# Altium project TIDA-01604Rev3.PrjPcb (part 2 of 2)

## Sheet PowerBoard.SchDoc
size 431 x 279 mm; Date: Not shown in title block; ApprovedBy: Not shown in title block; CheckedBy: Not shown in title block; Author: Not shown in title block; CompanyName: Not shown in title block; DrawnBy: G Wang; Engineer: Not shown in title block; Organization: Not shown in title block; Address1: Not shown in title block; Address2: Not shown in title block; Address3: Not shown in title block; Address4: Not shown in title block; DocumentNumber: 1; Revision: Use project parameter SCH_Rev; SheetNumber: 1; SheetTotal: 2; PageSetup: Record=PageOptions¦CenterHorizontal=True¦CenterVertical=True¦PrintScale=1.00¦XCorrection=1.00¦YCorrection=1.00¦PrintKind=0¦BorderSize=5000000¦LeftOffset=0¦BottomOffset=0¦Orientation=2¦PaperLength=1000¦PaperWidth=1000¦Scale=100¦PaperSource=15¦PrintQuality=600¦MediaType=1¦DitherType=10¦PaperKind=Letter¦PrintScaleMode=1
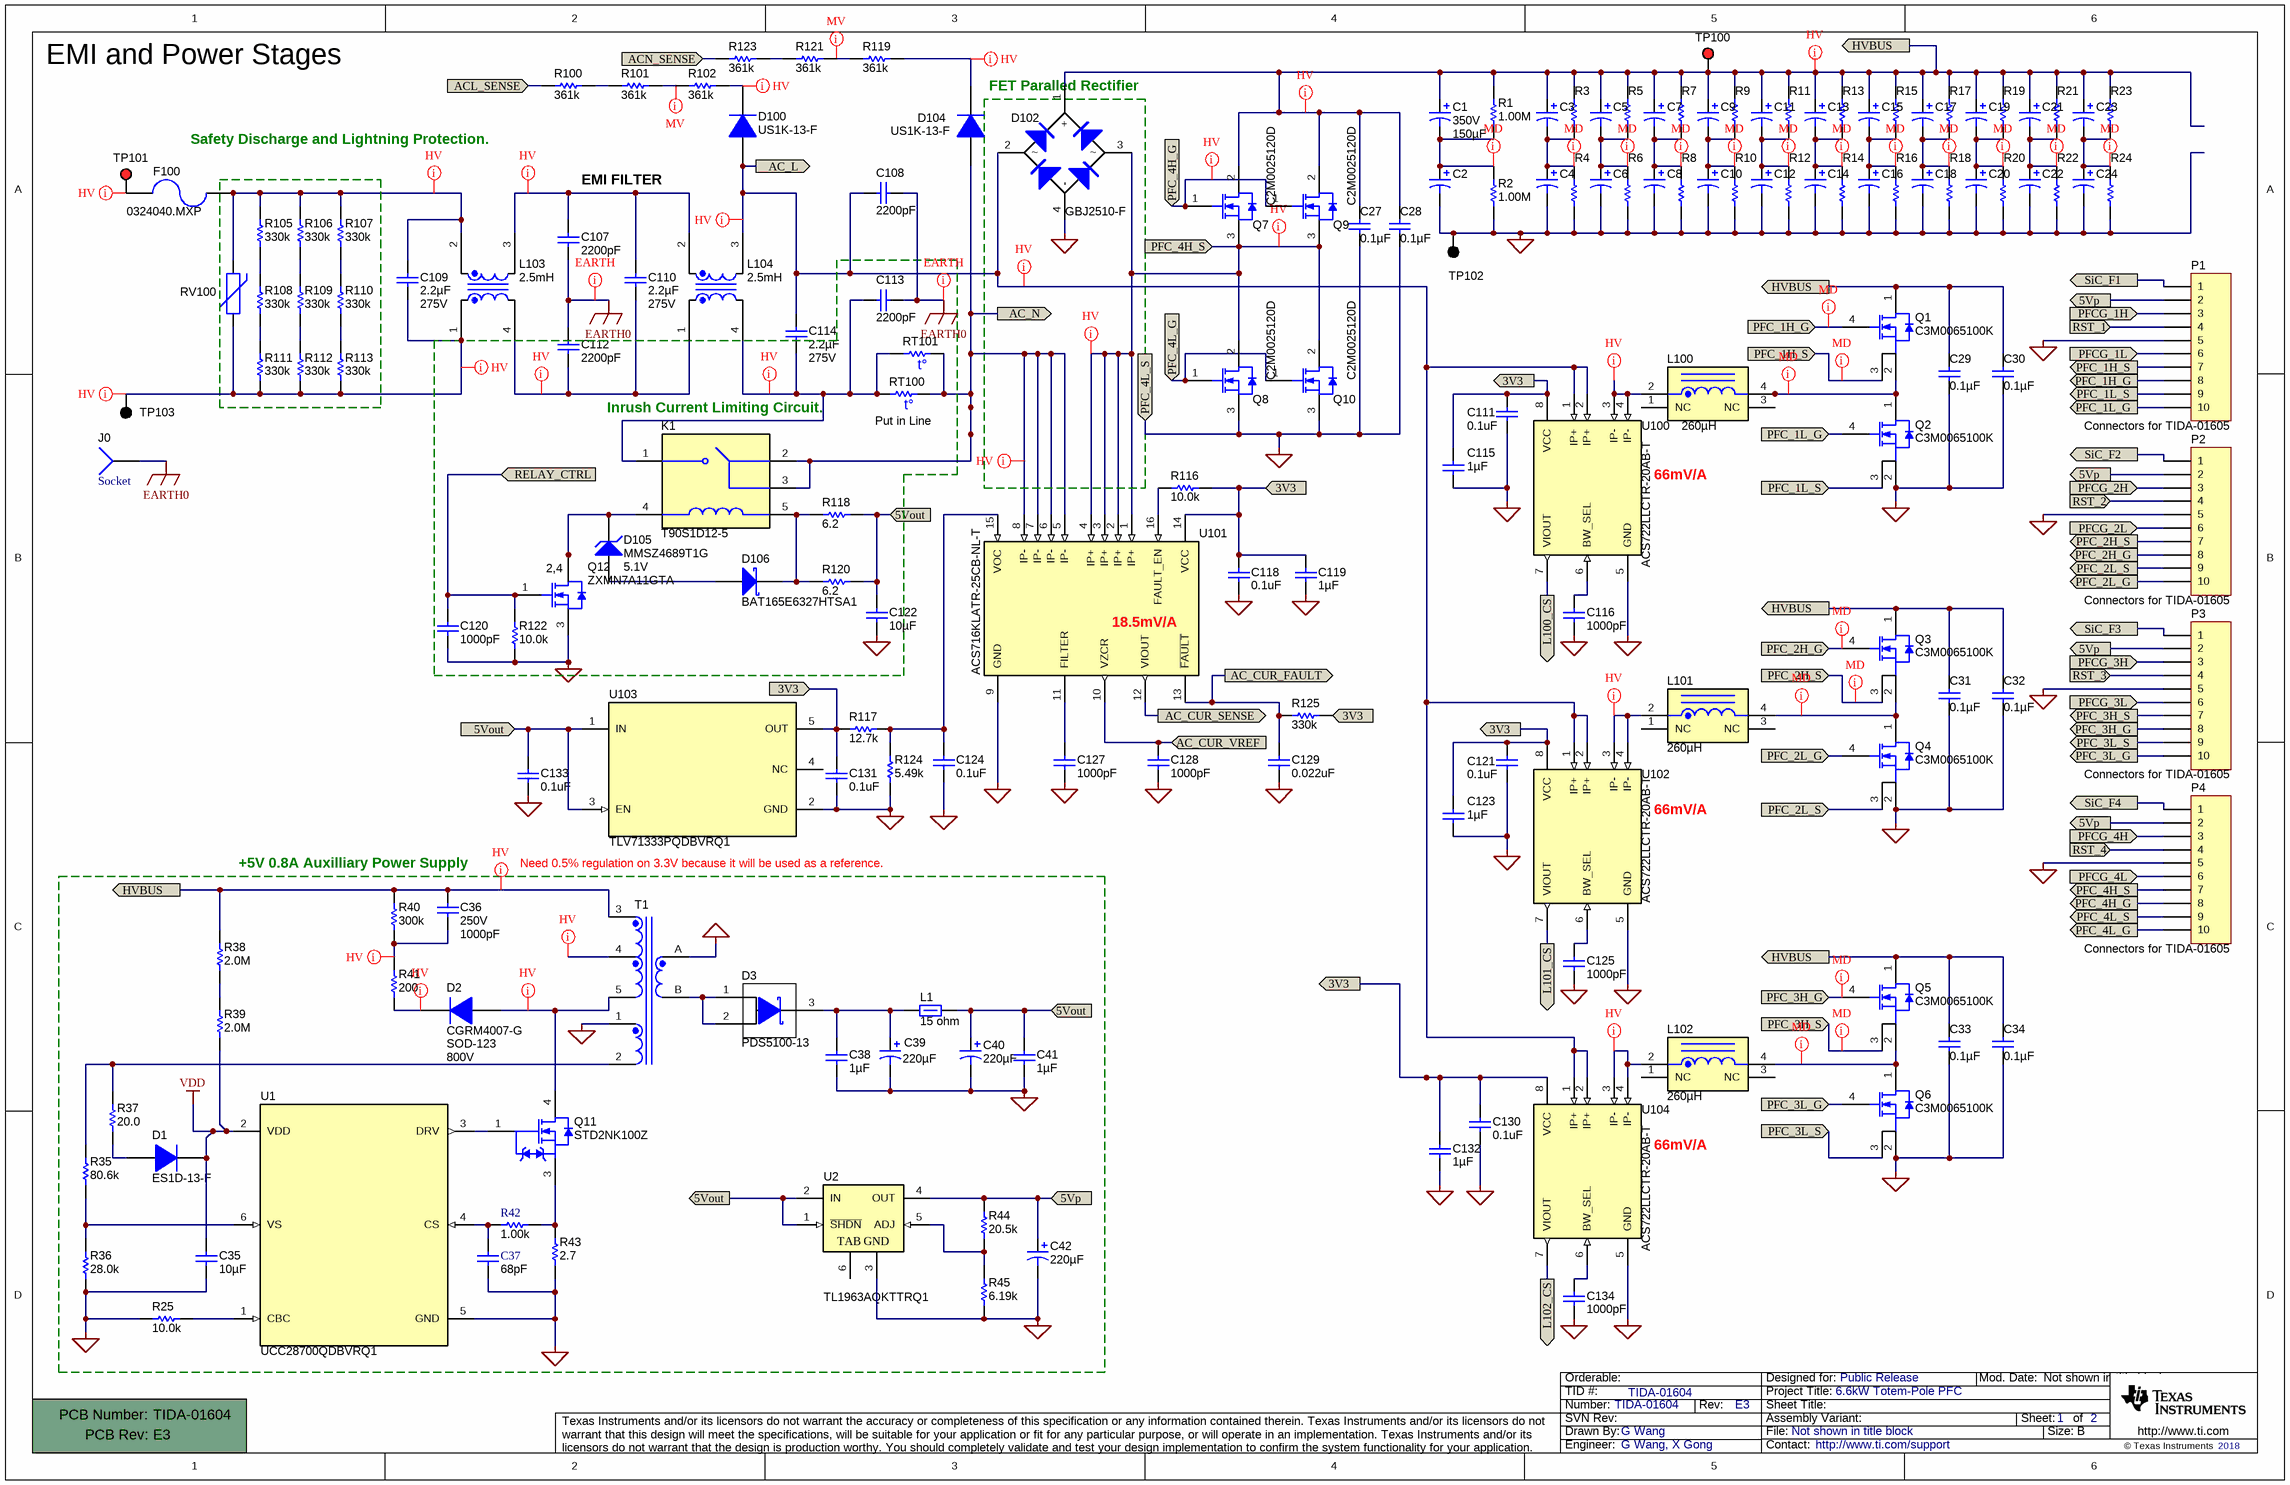
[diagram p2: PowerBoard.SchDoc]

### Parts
!PCB100  Printed Circuit Board  (value not drawn)  (mechanical)
C1  VDC_V: 350V  ValueDisplayed: 150µF  [BXW_1450x4500]  (hidden comment: 350BXW150MEFR14.5X45)
C2  350BXW150MEFR14.5X45  [BXW_1450x4500]  (value not drawn)
C3  350BXW150MEFR14.5X45  [BXW_1450x4500]  (value not drawn)
C4  350BXW150MEFR14.5X45  [BXW_1450x4500]  (value not drawn)
C5  350BXW150MEFR14.5X45  [BXW_1450x4500]  (value not drawn)
C6  350BXW150MEFR14.5X45  [BXW_1450x4500]  (value not drawn)
C7  350BXW150MEFR14.5X45  [BXW_1450x4500]  (value not drawn)
C8  350BXW150MEFR14.5X45  [BXW_1450x4500]  (value not drawn)
C9  350BXW150MEFR14.5X45  [BXW_1450x4500]  (value not drawn)
C10  350BXW150MEFR14.5X45  [BXW_1450x4500]  (value not drawn)
C11  350BXW150MEFR14.5X45  [BXW_1450x4500]  (value not drawn)
C12  350BXW150MEFR14.5X45  [BXW_1450x4500]  (value not drawn)
C13  350BXW150MEFR14.5X45  [BXW_1450x4500]  (value not drawn)
C14  350BXW150MEFR14.5X45  [BXW_1450x4500]  (value not drawn)
C15  350BXW150MEFR14.5X45  [BXW_1450x4500]  (value not drawn)
C16  350BXW150MEFR14.5X45  [BXW_1450x4500]  (value not drawn)
C17  350BXW150MEFR14.5X45  [BXW_1450x4500]  (value not drawn)
C18  350BXW150MEFR14.5X45  [BXW_1450x4500]  (value not drawn)
C19  350BXW150MEFR14.5X45  [BXW_1450x4500]  (value not drawn)
C20  350BXW150MEFR14.5X45  [BXW_1450x4500]  (value not drawn)
C21  350BXW150MEFR14.5X45  [BXW_1450x4500]  (value not drawn)
C22  350BXW150MEFR14.5X45  [BXW_1450x4500]  (value not drawn)
C23  350BXW150MEFR14.5X45  [BXW_1450x4500]  (value not drawn)
C24  350BXW150MEFR14.5X45  [BXW_1450x4500]  (value not drawn)
C27  ValueDisplayed: 0.1µF  [1812]  (hidden comment: VJ1812Y473KXEAT5Z)
C28  ValueDisplayed: 0.1µF  [1812]  (hidden comment: VJ1812Y473KXEAT5Z)
C29  ValueDisplayed: 0.1µF  [1812]  (hidden comment: VJ1812Y473KXEAT5Z)
C30  ValueDisplayed: 0.1µF  [1812]  (hidden comment: VJ1812Y473KXEAT5Z)
C31  ValueDisplayed: 0.1µF  [1812]  (hidden comment: VJ1812Y473KXEAT5Z)
C32  ValueDisplayed: 0.1µF  [1812]  (hidden comment: VJ1812Y473KXEAT5Z)
C33  ValueDisplayed: 0.1µF  [1812]  (hidden comment: VJ1812Y473KXEAT5Z)
C34  ValueDisplayed: 0.1µF  [1812]  (hidden comment: VJ1812Y473KXEAT5Z)
C35  ValueDisplayed: 10µF  [1206_180]  (hidden comment: GRM31CR71E106KA12L)
C36  VDC_V: 250V  ValueDisplayed: 1000pF  [0805_HV]  (hidden comment: C2012X7R2E102K085AA)
C37  ValueDisplayed: 68pF  [0603]  (hidden comment: 06035A680JAT2A)
C38  ValueDisplayed: 1µF  [0603]  (hidden comment: GRM185R60J105KE26D)
C39  ValueDisplayed: 220µF  [7343-30]  (hidden comment: 10TPE220ML)
C40  ValueDisplayed: 220µF  [7343-30]  (hidden comment: 10TPE220ML)
C41  ValueDisplayed: 1µF  [0603]  (hidden comment: GRM185R60J105KE26D)
C42  ValueDisplayed: 220µF  [7343-30]  (hidden comment: 10TPE220ML)
C107  ValueDisplayed: 2200pF  [E_900x700x900]  (hidden comment: DE6E3KJ222MN3A)
C108  ValueDisplayed: 2200pF  [E_900x700x900]  (hidden comment: DE6E3KJ222MN3A)
C109  ValueDisplayed: 2.2µF  Value2: 275V  [WCAP-FTX2_2600x1500x2500]  (hidden comment: 890324026034)
C110  ValueDisplayed: 2.2µF  Value2: 275V  [WCAP-FTX2_2600x1500x2500]  (hidden comment: 890324026034)
C111  ValueDisplayed: 0.1uF  [0402]  (hidden comment: GRM155R70J104KA01D)
C112  ValueDisplayed: 2200pF  [E_900x700x900]  (hidden comment: DE6E3KJ222MN3A)
C113  ValueDisplayed: 2200pF  [E_900x700x900]  (hidden comment: DE6E3KJ222MN3A)
C114  ValueDisplayed: 2.2µF  Value2: 275V  [WCAP-FTX2_2600x1500x2500]  (hidden comment: 890324026034)
C115  ValueDisplayed: 1µF  [0603]  (hidden comment: GRM185R60J105KE26D)
C116  ValueDisplayed: 1000pF  [0603]  (hidden comment: 06035A102KAT2A)
C118  ValueDisplayed: 0.1uF  [0402]  (hidden comment: GRM155R70J104KA01D)
C119  ValueDisplayed: 1µF  [0603]  (hidden comment: GRM185R60J105KE26D)
C120  ValueDisplayed: 1000pF  [0603]  (hidden comment: GRM188R71C102KA01D)
C121  ValueDisplayed: 0.1uF  [0402]  (hidden comment: GRM155R70J104KA01D)
C122  ValueDisplayed: 10µF  [0805_HV]  (hidden comment: 0805YD106KAT2A)
C123  ValueDisplayed: 1µF  [0603]  (hidden comment: GRM185R60J105KE26D)
C124  ValueDisplayed: 0.1uF  [0402]  (hidden comment: GRM155R70J104KA01D)
C125  ValueDisplayed: 1000pF  [0603]  (hidden comment: 06035A102KAT2A)
C127  ValueDisplayed: 1000pF  [0402]  (hidden comment: GRM155R60J102KA01D)
C128  ValueDisplayed: 1000pF  [0402]  (hidden comment: GRM155R60J102KA01D)
C129  ValueDisplayed: 0.022uF  [0402]  (hidden comment: GRM155R70J223KA01D)
C130  ValueDisplayed: 0.1uF  [0402]  (hidden comment: GRM155R70J104KA01D)
C131  ValueDisplayed: 0.1uF  [0402]  (hidden comment: GRM155R70J104KA01D)
C132  ValueDisplayed: 1µF  [0603]  (hidden comment: GRM185R60J105KE26D)
C133  ValueDisplayed: 0.1uF  [0402]  (hidden comment: GRM155R70J104KA01D)
C134  ValueDisplayed: 1000pF  [0603]  (hidden comment: 06035A102KAT2A)
D1  ES1D-13-F  [SMA]
D2  CGRM4007-G  Value2: 800V  [SOD-123]
D3  PDS5100-13  [POWERDI5]
D100  US1K-13-F  [SMA]
D102  GBJ2510-F  [GBJ]
D104  US1K-13-F  [SMA]
D105  MMSZ4689T1G  value 5.1V  [SOD-123]
D106  BAT165E6327HTSA1  [SOD-323]
F100  0324040.MXP  [FUSE_0325_Vertical]
J0  Socket  [PIN1]
K1  T90S1D12-5  [Relay_T90S1]
L1  ValueDisplayed: 15 ohm  [0603]  (hidden comment: MMZ1608R150ATA00)
L100  ValueDisplayed: 260µH  [G184014LF]  (hidden comment: G184014LF)
L101  ValueDisplayed: 260µH  [G184014LF]  (hidden comment: G184014LF)
L102  ValueDisplayed: 260µH  [G184014LF]  (hidden comment: G184014LF)
L103  ValueDisplayed: 2.5mH  [WE-CMBNC_XL]  (hidden comment: 7448052303)
L104  ValueDisplayed: 2.5mH  [WE-CMBNC_XL]  (hidden comment: 7448052303)
P1  PartNumber: Connectors for TIDA-01605  [Driver]  (hidden comment: driver)
P2  PartNumber: Connectors for TIDA-01605  [Driver]  (hidden comment: driver)
P3  PartNumber: Connectors for TIDA-01605  [Driver]  (hidden comment: driver)
P4  PartNumber: Connectors for TIDA-01605  [Driver]  (hidden comment: driver)
Q1  C3M0065100K  [TO-247-4]
Q2  C3M0065100K  [TO-247-4]
Q3  C3M0065100K  [TO-247-4]
Q4  C3M0065100K  [TO-247-4]
Q5  C3M0065100K  [TO-247-4]
Q6  C3M0065100K  [TO-247-4]
Q7  C2M0025120D  [TO-247]
Q8  C2M0025120D  [TO-247]
Q9  C2M0025120D  [TO-247]
Q10  C2M0025120D  [TO-247]
Q11  STD2NK100Z  [DPAK]
Q12  ZXMN7A11GTA  [SOT-223]
R1  ValueDisplayed: 1.00M  [1206]  (hidden comment: CRCW12061M00FKEA)
R2  ValueDisplayed: 1.00M  [1206]  (hidden comment: CRCW12061M00FKEA)
R3  CRCW12061M00FKEA  [1206]  (value not drawn)
R4  CRCW12061M00FKEA  [1206]  (value not drawn)
R5  CRCW12061M00FKEA  [1206]  (value not drawn)
R6  CRCW12061M00FKEA  [1206]  (value not drawn)
R7  CRCW12061M00FKEA  [1206]  (value not drawn)
R8  CRCW12061M00FKEA  [1206]  (value not drawn)
R9  CRCW12061M00FKEA  [1206]  (value not drawn)
R10  CRCW12061M00FKEA  [1206]  (value not drawn)
R11  CRCW12061M00FKEA  [1206]  (value not drawn)
R12  CRCW12061M00FKEA  [1206]  (value not drawn)
R13  CRCW12061M00FKEA  [1206]  (value not drawn)
R14  CRCW12061M00FKEA  [1206]  (value not drawn)
R15  CRCW12061M00FKEA  [1206]  (value not drawn)
R16  CRCW12061M00FKEA  [1206]  (value not drawn)
R17  CRCW12061M00FKEA  [1206]  (value not drawn)
R18  CRCW12061M00FKEA  [1206]  (value not drawn)
R19  CRCW12061M00FKEA  [1206]  (value not drawn)
R20  CRCW12061M00FKEA  [1206]  (value not drawn)
R21  CRCW12061M00FKEA  [1206]  (value not drawn)
R22  CRCW12061M00FKEA  [1206]  (value not drawn)
R23  CRCW12061M00FKEA  [1206]  (value not drawn)
R24  CRCW12061M00FKEA  [1206]  (value not drawn)
R25  ValueDisplayed: 10.0k  [0603]  (hidden comment: CRCW060310K0FKEA)
R35  ValueDisplayed: 80.6k  [0603]  (hidden comment: CRCW060380K6FKEA)
R36  ValueDisplayed: 28.0k  [0603]  (hidden comment: CRCW060328K0FKEA)
R37  ValueDisplayed: 20.0  [0603]  (hidden comment: RC0603FR-0720RL)
R38  ValueDisplayed: 2.0M  [1206]  (hidden comment: CRCW12062M00JNEA)
R39  ValueDisplayed: 2.0M  [1206]  (hidden comment: CRCW12062M00JNEA)
R40  ValueDisplayed: 300k  [1206]  (hidden comment: RC1206FR-07300KL)
R41  ValueDisplayed: 200  [0805_HV]  (hidden comment: ERJ-6GEYJ201V)
R42  value 1.00k  [0603]  (hidden comment: CRCW06031K00FKEA)
R43  ValueDisplayed: 2.7  [0805_HV]  (hidden comment: CRCW08052R70JNEA)
R44  ValueDisplayed: 20.5k  [0603]  (hidden comment: RC0603FR-0720K5L)
R45  ValueDisplayed: 6.19k  [0603]  (hidden comment: RC0603FR-076K19L)
R100  ValueDisplayed: 361k  [0805_HV]  (hidden comment: RT0805BRD07361KL)
R101  ValueDisplayed: 361k  [0805_HV]  (hidden comment: RT0805BRD07361KL)
R102  ValueDisplayed: 361k  [0805_HV]  (hidden comment: RT0805BRD07361KL)
R105  ValueDisplayed: 330k  [1206]  (hidden comment: CRCW1206330KJNEA)
R106  ValueDisplayed: 330k  [1206]  (hidden comment: CRCW1206330KJNEA)
R107  ValueDisplayed: 330k  [1206]  (hidden comment: CRCW1206330KJNEA)
R108  ValueDisplayed: 330k  [1206]  (hidden comment: CRCW1206330KJNEA)
R109  ValueDisplayed: 330k  [1206]  (hidden comment: CRCW1206330KJNEA)
R110  ValueDisplayed: 330k  [1206]  (hidden comment: CRCW1206330KJNEA)
R111  ValueDisplayed: 330k  [1206]  (hidden comment: CRCW1206330KJNEA)
R112  ValueDisplayed: 330k  [1206]  (hidden comment: CRCW1206330KJNEA)
R113  ValueDisplayed: 330k  [1206]  (hidden comment: CRCW1206330KJNEA)
R116  value 10.0k  [0402]  (hidden comment: CRCW040210K0FKED)
R117  value 12.7k  [0402]  (hidden comment: CRCW040212K7FKED)
R118  ValueDisplayed: 6.2  [1206]  (hidden comment: CRCW12066R20JNEA)
R119  ValueDisplayed: 361k  [0805_HV]  (hidden comment: RT0805BRD07361KL)
R120  ValueDisplayed: 6.2  [1206]  (hidden comment: CRCW12066R20JNEA)
R121  ValueDisplayed: 361k  [0805_HV]  (hidden comment: RT0805BRD07361KL)
R122  value 10.0k  [0603]  (hidden comment: RC0603FR-0710KL)
R123  ValueDisplayed: 361k  [0805_HV]  (hidden comment: RT0805BRD07361KL)
R124  value 5.49k  [0402]  (hidden comment: CRCW04025K49FKED)
R125  value 330k  [0402]  (hidden comment: CRCW0402330KJNED)
RT100  B59751B0120A070  [TDK_B751]  (value not drawn)
RT101  B59751B0120A070  [TDK_B751]  (value not drawn)
RV100  S10K275E2  [VAR_S10K275E2]  (value not drawn)
T1  7508110162  [WURTH_7508110162]  (value not drawn)
TP100  5000  [Keystone5000]  (value not drawn)
TP101  5000  [Keystone5000]  (value not drawn)
TP102  5001  [Keystone5001]  (value not drawn)
TP103  5001  [Keystone5001]  (value not drawn)
U1  UCC28700QDBVRQ1  [DBV0006A_N]
U2  TL1963AQKTTRQ1  [KTT0005A_N]
U100  ACS722LLCTR-20AB-T  [SOIC-8]
U101  ACS716KLATR-25CB-NL-T  [SOIC-16]
U102  ACS722LLCTR-20AB-T  [SOIC-8]
U103  TLV71333PQDBVRQ1  [DBV0005A_N]
U104  ACS722LLCTR-20AB-T  [SOIC-8]

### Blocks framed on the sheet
FET Paralled Rectifier: D102
Inrush Current Limiting Circuit.: C112 C113 C120 C122 D105 D106 K1 Q12 R118 R120 R122 RT100 RT101
+5V 0.8A Auxilliary Power Supply: C35-C42 D1-D3 L1 Q11 R25 R35-R45 T1 U1 U2

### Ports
3V3, 5Vout, 5Vp, AC_CUR_FAULT, AC_CUR_SENSE, AC_CUR_VREF, AC_L, AC_N, ACL_SENSE, ACN_SENSE, HVBUS, L100_CS (out), L101_CS (out), L102_CS (out), PFC_1H_G (in), PFC_1H_G (out), PFC_1H_S (in), PFC_1H_S (out), PFC_1L_G (in), PFC_1L_G (out), PFC_1L_S (in), PFC_1L_S (out), PFC_2H_G (in), PFC_2H_G (out), PFC_2H_S (in), PFC_2H_S (out), PFC_2L_G (in), PFC_2L_G (out), PFC_2L_S (in), PFC_2L_S (out), PFC_3H_G (in), PFC_3H_G (out), PFC_3H_S (in), PFC_3H_S (out), PFC_3L_G (in), PFC_3L_G (out), PFC_3L_S (in), PFC_3L_S (out), PFC_4H_G (in), PFC_4H_G (out), PFC_4H_S (in), PFC_4H_S (out), PFC_4L_G (in), PFC_4L_G (out), PFC_4L_S, PFCG_1H (in), PFCG_1L (in), PFCG_2H (in), PFCG_2L (in), PFCG_3H (in), PFCG_3L (in), PFCG_4H (in), PFCG_4L (in), RELAY_CTRL (in), RST_1 (in), RST_2 (in), RST_3 (in), RST_4 (in), SiC_F1 (out), SiC_F2 (out), SiC_F3 (out), SiC_F4 (out)

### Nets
EARTH0: C107.2 C108.1 C112.1 C113.1 J0.1
PGND: C2.2(-) C4.2(-) C6.2(-) C8.2(-) C10.2(-) C12.2(-) C14.2(-) C16.2(-) C18.2(-) C20.2(-) C22.2(-) C24.2(-) C27.2 C28.2 C29.2 C30.2 C31.2 C32.2 C33.2 C34.2 C35.2 C37.2 C38.2 C39.2(-) C40.2(-) C41.2 C42.2(-) C111.2 C115.2 C116.2 C118.2 C119.2 C120.2 C121.2 C122.2 C123.2 C124.2 C125.2 C127.2 C128.2 C129.1 C130.2 C131.2 C132.2 C133.2 C134.2 D102.4(-) P1.5 P2.5 P3.5 P4.5 P4.9 Q2.2(S) Q4.2(S) Q6.2(S) Q8.3(S) Q10.3(S) Q12.3(S) R2.1 R4.1 R6.1 R8.1 R10.1 R12.1 R14.1 R16.1 R18.1 R20.1 R22.1 R24.1 R25.1 R36.1 R43.1 R45.1 R122.1 R124.1 T1.1 T1.A TP102.1 U1.5(GND) U2.3(GND) U100.5(GND) U101.9(GND) U102.5(GND) U103.2(GND) U104.5(GND) ; port PFC_4L_S
VDD: C35.1 D1.1(K) R39.1 U1.2(VDD)
3V3: C111.1 C115.1 C118.1 C119.1 C121.1 C123.1 C130.1 C131.1 C132.1 R116.2 R117.1 R125.1 U100.8(VCC) U101.14(VCC) U102.8(VCC) U103.5(OUT) U104.8(VCC) ; port 3V3
5Vout: C40.1(+) C41.1 C122.1 C133.1 L1.2 R118.2 R120.2 U2.1(~{SHDN}) U2.2(IN) U103.1(IN) U103.3(EN) ; port 5Vout
5Vp: C42.1(+) P1.2 P2.2 P3.2 P4.2 R44.2 U2.4(OUT) ; port 5Vp
AC_CUR_FAULT: C129.2 R125.2 U101.13(~{FAULT}) ; port AC_CUR_FAULT
AC_CUR_SENSE: U101.12(VIOUT) ; port AC_CUR_SENSE
AC_CUR_VREF: C128.1 U101.10(VZCR) ; port AC_CUR_VREF
AC_L: C108.2 C114.1 D100.2(A) D102.2 L104.3 U100.1(IP+) U100.2(IP+) U102.1(IP+) U102.2(IP+) U104.1(IP+) U104.2(IP+) ; port AC_L
AC_N: D104.2(A) K1.2 K1.3 RT100.2 RT101.2 U101.5(IP-) U101.6(IP-) U101.7(IP-) U101.8(IP-) ; port AC_N
ACL_SENSE: R100.1 ; port ACL_SENSE
ACN_SENSE: R123.1 ; port ACN_SENSE
HVBUS: C1.1(+) C3.1(+) C5.1(+) C7.1(+) C9.1(+) C11.1(+) C13.1(+) C15.1(+) C17.1(+) C19.1(+) C21.1(+) C23.1(+) C27.1 C28.1 C29.1 C30.1 C31.1 C32.1 C33.1 C34.1 C36.1 D102.1(+) Q1.1(D) Q3.1(D) Q5.1(D) Q7.2(D) Q9.2(D) R1.2 R3.2 R5.2 R7.2 R9.2 R11.2 R13.2 R15.2 R17.2 R19.2 R21.2 R23.2 R38.2 R40.2 T1.3 TP100.1 ; port HVBUS
L100_CS: U100.7(VIOUT) ; port L100_CS
L101_CS: U102.7(VIOUT) ; port L101_CS
L102_CS: U104.7(VIOUT) ; port L102_CS
PFC_1H_G: P1.8 Q1.4(G) ; port PFC_1H_G
PFC_1H_S: P1.7 Q1.3(KS) ; port PFC_1H_S
PFC_1L_G: P1.10 Q2.4(G) ; port PFC_1L_G
PFC_1L_S: P1.9 Q2.3(KS) ; port PFC_1L_S
PFC_2H_G: P2.8 Q3.4(G) ; port PFC_2H_G
PFC_2H_S: P2.7 Q3.3(KS) ; port PFC_2H_S
PFC_2L_G: P2.10 Q4.4(G) ; port PFC_2L_G
PFC_2L_S: P2.9 Q4.3(KS) ; port PFC_2L_S
PFC_3H_G: P3.8 Q5.4(G) ; port PFC_3H_G
PFC_3H_S: P3.7 Q5.3(KS) ; port PFC_3H_S
PFC_3L_G: P3.10 Q6.4(G) ; port PFC_3L_G
PFC_3L_S: P3.9 Q6.3(KS) ; port PFC_3L_S
PFC_4H_G: P4.8 Q7.1(G) Q9.1(G) ; port PFC_4H_G
PFC_4H_S: D102.3 P4.7 Q7.3(S) Q8.2(D) Q9.3(S) Q10.2(D) U101.1(IP+) U101.2(IP+) U101.3(IP+) U101.4(IP+) ; port PFC_4H_S
PFC_4L_G: P4.10 Q8.1(G) Q10.1(G) ; port PFC_4L_G
PFCG_1H: P1.3 ; port PFCG_1H
PFCG_1L: P1.6 ; port PFCG_1L
PFCG_2H: P2.3 ; port PFCG_2H
PFCG_2L: P2.6 ; port PFCG_2L
PFCG_3H: P3.3 ; port PFCG_3H
PFCG_3L: P3.6 ; port PFCG_3L
PFCG_4H: P4.3 ; port PFCG_4H
PFCG_4L: P4.6 ; port PFCG_4L
RELAY_CTRL: C120.1 Q12.1(G) R122.2 ; port RELAY_CTRL
RST_1: P1.4 ; port RST_1
RST_2: P2.4 ; port RST_2
RST_3: P3.4 ; port RST_3
RST_4: P4.4 ; port RST_4
SiC_F1: P1.1 ; port SiC_F1
SiC_F2: P2.1 ; port SiC_F2
SiC_F3: P3.1 ; port SiC_F3
SiC_F4: P4.1 ; port SiC_F4
NetC1_2: C1.2(-) C2.1(+) R1.1 R2.2
NetC3_2: C3.2(-) C4.1(+) R3.1 R4.2
NetC5_2: C5.2(-) C6.1(+) R5.1 R6.2
NetC7_2: C7.2(-) C8.1(+) R7.1 R8.2
NetC9_2: C9.2(-) C10.1(+) R9.1 R10.2
NetC11_2: C11.2(-) C12.1(+) R11.1 R12.2
NetC13_2: C13.2(-) C14.1(+) R13.1 R14.2
NetC15_2: C15.2(-) C16.1(+) R15.1 R16.2
NetC17_2: C17.2(-) C18.1(+) R17.1 R18.2
NetC19_2: C19.2(-) C20.1(+) R19.1 R20.2
NetC21_2: C21.2(-) C22.1(+) R21.1 R22.2
NetC23_2: C23.2(-) C24.1(+) R23.1 R24.2
NetC36_2: C36.2 R40.1 R41.2
NetC37_1: C37.1 R42.1 U1.4(CS)
NetC38_1: C38.1 C39.1(+) D3.3(K) L1.1
NetC107_1: C107.1 C110.1 L103.3 L104.2
NetC109_1: C109.1 F100.1 L103.2 R105.2 R106.2 R107.2 RV100.2
NetC109_2: C109.2 L103.1 R111.1 R112.1 R113.1 RV100.1 TP103.1
NetC110_2: C110.2 C112.2 L103.4 L104.1
NetC113_2: C113.2 C114.2 K1.1 L104.4 RT100.1 RT101.1
NetC116_1: C116.1 U100.6(BW_SEL)
NetC124_1: C124.1 R117.2 R124.2 U101.15(VOC)
NetC125_1: C125.1 U102.6(BW_SEL)
NetC127_1: C127.1 U101.11(FILTER)
NetC134_1: C134.1 U104.6(BW_SEL)
NetD1_2: D1.2(A) R37.2
NetD2_1: D2.1(K) R41.1
NetD2_2: D2.2(A) Q11.4(D) T1.5
NetD3_1: D3.1(A) D3.2(A) T1.B
NetD100_1: D100.1(K) R102.2
NetD104_1: D104.1(K) R119.2
NetD105_1: D105.1(K) K1.4 Q12.2(D) Q12.4(D)
NetD105_2: D105.2(A) D106.2(A)
NetD106_1: D106.1(K) K1.5 R118.1 R120.1
NetF100_2: F100.2 TP101.1
NetL100_2: L100.2 U100.3(IP-) U100.4(IP-)
NetL100_4: L100.4 Q1.2(S) Q2.1(D)
NetL101_2: L101.2 U102.3(IP-) U102.4(IP-)
NetL101_4: L101.4 Q3.2(S) Q4.1(D)
NetL102_2: L102.2 U104.3(IP-) U104.4(IP-)
NetL102_4: L102.4 Q5.2(S) Q6.1(D)
NetQ11_1: Q11.1(G) U1.3(DRV)
NetQ11_3: Q11.3(S) R42.2 R43.2
NetR25_2: R25.2 U1.1(CBC)
NetR35_1: R35.1 R36.2 U1.6(VS)
NetR35_2: R35.2 R37.1 T1.2
NetR38_1: R38.1 R39.2
NetR44_1: R44.1 R45.2 U2.5(ADJ)
NetR100_2: R100.2 R101.1
NetR101_2: R101.2 R102.1
NetR105_1: R105.1 R108.2
NetR106_1: R106.1 R109.2
NetR107_1: R107.1 R110.2
NetR108_1: R108.1 R111.2
NetR109_1: R109.1 R112.2
NetR110_1: R110.1 R113.2
NetR116_1: R116.1 U101.16(FAULT_EN)
NetR119_1: R119.1 R121.2
NetR121_1: R121.1 R123.2

Not connected (* = marked no-connect by the designer): L100 1(NC) 3(NC); L101 1(NC) 3(NC); L102 1(NC) 3(NC); T1 4; U2 6(TAB); U103 4(NC)

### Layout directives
net class HV: AC_L, AC_N, HVBUS, NetC36_2, NetC107_1, NetC109_1, NetC109_2, NetC110_2, NetC113_2, NetD2_1, NetD2_2, NetD100_1, NetD104_1, NetF100_2, NetL100_2, NetL101_2, NetL102_2, NetT1_4, PFC_4H_G, PFC_4H_S
net class MD: NetC1_2, NetC3_2, NetC5_2, NetC7_2, NetC9_2, NetC11_2, NetC13_2, NetC15_2, NetC17_2, NetC19_2, NetC21_2, NetC23_2, NetL100_4, NetL101_4, NetL102_4, PFC_1H_G, PFC_1H_S, PFC_2H_G, PFC_2H_S, PFC_3H_G, PFC_3H_S
net class MV: NetR101_2, NetR119_1
net class EARTH: EARTH0

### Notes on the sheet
- EMI and Power Stages
- Safety Discharge and Lightning Protection.
- (near C107) EMI FILTER
- (near RT100) Put in Line
- (near U100) 66mV/A
- (near U101) 18.5mV/A
- (near U102) 66mV/A
- Need 0.5% regulation on 3.3V because it will be used as a reference.
- (near U104) 66mV/A

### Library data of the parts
!PCB100 = PCB: Manufacturer: Any; PartNumber: TIDA-01604; SymbolCreator: a0412235
C1 = CMP-0077904-1: CAP, AL, 150 µF, 350 V, +/- 20%, TH; Manufacturer: Rubycon; IRMS_A: 9.7dA; SizeAreaWB_mm2: 272.25; SizeArea_mm2: 210.25; AEC Qualified: N; AEC Category: Q200; Value: 150uF; TaMax_C: 105°C; SizeZ_mm: 47; Polarized: Y; TaMin_C: -40°C; SizeY_mm: 14.5; U/M: EA; CompType: Capacitor; Cap_Case: 14.5x45mm
C2-C24 = CMP-0077904-1: CAP, AL, 150 µF, 350 V, +/- 20%, TH; Manufacturer: Rubycon; Cap_F: 150µF; IRMS_A: 9.7dA; SizeAreaWB_mm2: 272.25; SizeArea_mm2: 210.25; AEC Qualified: N; AEC Category: Q200; Value: 150uF; TaMax_C: 105°C; SizeZ_mm: 47; Polarized: Y; TaMin_C: -40°C; VDC_V: 350V; SizeY_mm: 14.5; U/M: EA; CompType: Capacitor; Cap_Case: 14.5x45mm
C27-C34 = VJ1812Y473KXEAT5Z: CAP, CERM, 0.1µF, 1kV,+/- 10%, X7R, 1812; PartNumber: C1812C104KDRAC7800; Manufacturer: KEMET; Polarized: N; CompType: Capacitor; Value: 0.1uF; U/M: EA; Cap_F: 0.000000047; Tolerance_%: 10; VDC_V: 1000; Value2: 1000V; TaMin_C: -55; TaMax_C: 125; SizeArea_mm2: 14.4; SizeAreaWB_mm2: 23.1; SizeX_mm: 4.5; SizeY_mm: 3.2; SizeZ_mm: 1.35; AEC Category: Q200
C35 = GRM31CR71E106KA12L: CAP, CERM, 10 µF, 25 V,+/- 10%, X7R, 1206; Manufacturer: MuRata; Polarized: N; CompType: Capacitor; Value: 10uF; U/M: EA; Cap_F: 0.00001; Tolerance_%: 10; VDC_V: 25; Value2: 25V; TaMin_C: -55; TaMax_C: 125; Cap_Case: 1206; SizeArea_mm2: 5.12; SizeAreaWB_mm2: 10.92; SizeX_mm: 3.2; SizeY_mm: 1.6; SizeZ_mm: 1.8; AEC Category: Q200; Green_Lifecycle: Active; Green_REACh: Passed
C36 = CMP-0064943-2: CAP, CERM, 1000 pF, 250 V,+/- 10%, X7R, 0805; Manufacturer: TDK; TaMin_C: -55°C; Polarized: N; SizeAreaWB_mm2: 6.75; Value1: Unknown; U/M: EA; Value: 1000pF; TaMax_C: 125°C; SizeZ_mm: 1.45; SizeX_mm: 2; SizeY_mm: 1.25; Cap_Case: 0805; SizeArea_mm2: 2.5; CompType: Capacitor; Cap_F: 1nF; AEC Category: Q200
C37 = 06035A680JAT2A: CAP, CERM, 68pF, 50V, +/-5%, C0G/NP0, 0603; Manufacturer: AVX; Polarized: N; CompType: Capacitor; U/M: EA; Cap_F: 0.000000000068; Tolerance_%: 5; ESR_Ohm: 0.144; Value1: 0.144 ohm; VDC_V: 50; TaMin_C: -55; TaMax_C: 125
C38 C41 C115 C119 C123 C132 = GRM185R60J105KE26D: CAP, CERM, 1uF, 6.3V, +/-10%, X5R, 0603; Manufacturer: MuRata; Polarized: N; CompType: Capacitor; U/M: EA; Cap_F: 0.000001; Tolerance_%: 10; Value1: Unknown; VDC_V: 6.3; TaMin_C: -55; TaMax_C: 85
C39 C40 C42 = 10TPE220ML: CAP, Tantalum Polymer, 220 µF, 10 V,+/- 20%, 0.025 ohm, 7343-30 SMD; Manufacturer: Panasonic; Polarized: Y; CompType: Capacitor; Value: 220uF; U/M: EA; Cap_F: 0.00022; Tolerance_%: 20; VDC_V: 10; Value2: 10V; ESR_ohm: 0.025; IRMS_A: 2.4; TaMin_C: -55; TaMax_C: 105; SizeAreaWB_mm2: 58.59; SizeArea_mm2: 31.39; SizeX_mm: 7.3; SizeY_mm: 4.3; SizeZ_mm: 3; AEC Category: Q200; AEC Qualified: N; Green_Lifecycle: Active; Green_REACh: Passed
C107 C108 C112 C113 = DE6E3KJ222MN3A: CAP, CERM, 2200 pF, 300 V, +/- 20%, E, TH, 2- Leads, Body 9x7mm, Pin Spacing 7.5mm; Manufacturer: MuRata; Polarized: N; CompType: Capacitor; Value: 2200pF; U/M: EA; Cap_F: 0.0000000022; Tolerance_%: 20; Value1: Unknown; VDC_V: 300; Value2: 300V; TaMin_C: -40; TaMax_C: 125; Cap_Case: 9x7x9mm; SizeArea_mm2: 63; SizeAreaWB_mm2: 99; SizeX_mm: 9; SizeY_mm: 7; SizeZ_mm: 12; AEC Category: Q200
C109 C110 C114 = 890324026034: CAP, Film, 2.2 µF, 275 V, +/- 10%, TH; Manufacturer: Wurth Elektronik; Polarized: N; CompType: Capacitor; Value: 2.2uF; U/M: EA; Cap_F: 0.0000022; Tolerance_%: 10; Value1: Unknown; VDC_V: 275; TaMin_C: -40; TaMax_C: 105; Cap_Case: 26x15x25mm; AEC Category: Q200
C111 C118 C121 C124 C130 C131 C133 = GRM155R70J104KA01D: CAP, CERM, 0.1uF, 6.3V, +/-10%, X7R, 0402; Manufacturer: MuRata; Polarized: N; CompType: Capacitor; U/M: EA; Cap_F: 0.0000001; Tolerance_%: 10; Value1: Unknown; VDC_V: 6.3; TaMin_C: -55; TaMax_C: 125
C116 C125 C134 = 06035A102KAT2A: CAP, CERM, 1000 pF, 50 V, +/- 10%, C0G/NP0, 0603; Manufacturer: AVX; Polarized: N; CompType: Capacitor; Value: 1000pF; U/M: EA; Cap_F: 0.000000001; Tolerance_%: 10; ESR_ohm: 0.048; Value1: 0.048 ohm; VDC_V: 50; Value2: 50V; TaMin_C: -55; TaMax_C: 125; SizeArea_mm2: 1.28; SizeAreaWB_mm2: 4.68; SizeX_mm: 1.6; SizeY_mm: 0.8; SizeZ_mm: 1; AEC Category: Q200
C120 = GRM188R71C102KA01D: CAP, CERM, 1000pF, 16V, +/-10%, X7R, 0603; Manufacturer: MuRata; Polarized: N; CompType: Capacitor; U/M: EA; Cap_F: 0.000000001; Tolerance_%: 10; Value1: Unknown; VDC_V: 16; TaMin_C: -55; TaMax_C: 125
C122 = 0805YD106KAT2A: CAP, CERM, 10 µF, 16 V,+/- 10%, X5R, 0805; Manufacturer: AVX; Polarized: N; CompType: Capacitor; Value: 10uF; U/M: EA; Cap_F: 0.00001; Tolerance_%: 10; VDC_V: 16; Value2: 16V; TaMin_C: -55; TaMax_C: 85; Cap_Case: 0805; SizeArea_mm2: 2.5; SizeAreaWB_mm2: 6.75; SizeX_mm: 2; SizeY_mm: 1.25; SizeZ_mm: 1.45; AEC Category: Q200; Green_Lifecycle: Active; Green_REACh: Passed
C127 C128 = GRM155R60J102KA01D: CAP, CERM, 1000pF, 6.3V, +/-10%, X5R, 0402; Manufacturer: MuRata; Polarized: N; CompType: Capacitor; U/M: EA; Cap_F: 0.000000001; Tolerance_%: 10; Value1: Unknown; VDC_V: 6.3; TaMin_C: -55; TaMax_C: 85
C129 = GRM155R70J223KA01D: CAP, CERM, 0.022uF, 6.3V, +/-10%, X7R, 0402; Manufacturer: MuRata; Polarized: N; CompType: Capacitor; U/M: EA; Cap_F: 0.000000022; Tolerance_%: 10; Value1: Unknown; VDC_V: 6.3; TaMin_C: -55; TaMax_C: 125
D1 = ES1D-13-F: Diode, Ultrafast, 200 V, 1 A, SMA; Manufacturer: Diodes Inc.; U/M: EA; Vf_V: 0.92; Value: 200V; Value1: 1A; Value2: 0.92V; Io_A: 1; Vr_V: 200; TJmax_C: 150; RJC_CperW: 25; AEC Category: Q101
D2 = US1M-13-F: Diode, Ultrafast, 800V, 1A, SMA; Manufacturer: Diodes Inc.; Value: 1.7V; U/M: EA; Vf_V: 1.7; Io_A: 1; Vr_V: 800; TJmax_C: 150; RJC_CperW: 30
D3 = CMP-0077048-1: Diode, Schottky, 100 V, 5 A, PowerDI5; Manufacturer: Diodes Inc.; SizeAreaWB_mm2: 49.56; Vr_V: 100V; SizeArea_mm2: 24.96; TJmax_C: 150°C; AEC Category: Q101; Value: 100V; SizeZ_mm: 1.05; Green_REACh: Incomplete; Io_A: 5A; Vf_V: 7.9dV; SizeY_mm: 3.9; Value2: 0.79V; Green_Lifecycle: Not Set; U/M: EA; SizeX_mm: 6.4
D100 D104 = US1K-13-F: Diode, Fast Rectifier, 800 V, 1 A, SMA; Manufacturer: Diodes Inc.; U/M: EA; Vf_V: 1.7; Value: 800V; Value1: 1A; Value2: 1.7V; Io_A: 1; Vr_V: 800; TJmax_C: 150; AEC Category: Q101
D102 = GBJ2510-F: Diode, Switching-Bridge, 1000 V, 25 A, TH; Manufacturer: Diodes Inc.; U/M: EA; Vf_V: 1.05; Value: 1000V; Value1: 25A; Value2: 1.05V; Io_A: 25; Vr_V: 1000; TJmax_C: 150; RJC_CperW: 0.6; SizeAreaWB_mm2: 211.2; SizeArea_mm2: 138; SizeX_mm: 30; SizeY_mm: 4.6; SizeZ_mm: 24; AEC Category: Q101; AEC Qualified: N
D105 = MMSZ4689T1G: Diode, Zener, 5.1 V, 500 mW, SOD-123; Manufacturer: ON Semiconductor; SymbolCreator: a0412235; U/M: EA; Power_W: 0.5; Vz_V: 5.1; Value1: 0.5W; RJA_CperW: 340; SizeAreaWB_mm2: 13.095; SizeArea_mm2: 6.545; SizeX_mm: 3.85; SizeY_mm: 1.7; SizeZ_mm: 1.35; AEC Category: Q101
D106 = BAT165E6327HTSA1: Diode, Schottky, 40 V, 0.75 A, AEC-Q101, SOD-323; Manufacturer: Infineon Technologies; U/M: EA; Vf_V: 0.74; Value: 40V; Value1: 0.75A; Value2: 0.74V; Io_A: 0.75; Vr_V: 40; TJmax_C: 150; SizeAreaWB_mm2: 8.695; SizeArea_mm2: 3.645; SizeX_mm: 2.7; SizeY_mm: 1.35; SizeZ_mm: 1; AEC Category: Q101; AEC Qualified: Y; Green_Lifecycle: Not Set; Green_REACh: Incomplete
F100 = CMP-0003448-2: Fuse, 40 A, 250 VAC, 150 VDC, TH; Manufacturer: Littelfuse; Irating_A: 40A; Interrupt_AC: 400A; VAC_V: 250V; VDC_V: 60V; Rtyp_Ohm: 3.4m; MeltingTyp: 575
K1 = T90S1D12-5: Relay, SPST-NO (1 Form A), 30 A, 5 V, TH; Manufacturer: TE Connectivity; SymbolCreator: Altium; SizeAreaWB_mm2: 1008.2718; SizeArea_mm2: 884.8918; SizeX_mm: 27.43; SizeY_mm: 32.26; SizeZ_mm: 20.4; Coil Current_A: 0.185; Coil Power_W: 0.9; Coil Resistance_ohm: 27; Coil Type: Non Latching; Coil Voltage_VDC: 5; Contact Rating_A: 30; Turn Off Voltage (Min)_VDC: 0.5; Turn On Voltage (Max)_VDC: 3.75; Time Operate (s): 0.015
L1 = MMZ1608R150ATA00: Ferrite Bead, 15 ohm @ 100 MHz, 1.5 A, 0603; Manufacturer: TDK; Value: 15 ohm; Imax_A: 1.5; DCR_ohm: 0.05; Value1: 0.05 ohm; Value2: 1.5A; SizeAreaWB_mm2: 4.68; SizeArea_mm2: 1.28; SizeX_mm: 1.6; SizeY_mm: 0.8; SizeZ_mm: 1; ZTyp@100MHz_Ohm: 15; Green_Lifecycle: Active; Green_REACh: Passed
L100-L102 = CMP-0082528-1: Inductor, Toroid, 260 µH, 0.038 ohm, TH; Manufacturer: GCI Technologies; SizeAreaWB_mm2: 1139.2; SizeArea_mm2: 1003.0; AEC Qualified: N; AEC Category: Q200; Value: 260uH; SizeZ_mm: 44.5; SizeY_mm: 42.5; Value2: A; DCR_ohm: 0.038; SizeX_mm: 23.6
L103 L104 = 7448052303: CMC 2.5MH 25A 2LN TH; PartNumber: 7448052502; Manufacturer: Wurth Elektronik; SymbolCreator: a0799628; CompType: Coupled Inductor
P1-P4 = Header 10: Connectors for driver daughter card (include one PPPC032LFBN-RC and two PPPC021LFBN-RC); Manufacturer: Sullins Connector Solutions
Q1-Q6 = CMP-0067575-2: MOSFET, N-CH, 1000 V, 35 A, TO-247-4; Manufacturer: Cree; Alternate Manufacturer: None; Value2: 35 nC; Value1: ? ohm; SizeX_mm: 15.94; SizeY_mm: 5.02; SizeZ_mm: 27.97; AEC Qualified: N; Value: 1000V; SizeArea_mm2: 80.0188; AEC Category: Q101; SizeAreaWB_mm2: 125.9388; U/M: EA; VdsMax_V: 1kV; Vgs_V: 19V; IdsMax_A: 35A; QgTyp_nC: 35.0
Q7-Q10 = IPW60R045CP: MOSFET, N-CH, 1200 V, 90 A, TO-247; Manufacturer: Cree; Alternate Manufacturer: None; U/M: EA; ChType: N; Value: 1200V; QgTyp_nC: 150; IdsMax_A: 60; SizeAreaWB_mm2: 123.2; SizeArea_mm2: 78; SizeX_mm: 15.6; SizeY_mm: 5; SizeZ_mm: 25; AEC Category: Q101; Green_Lifecycle: Not Set; Green_REACh: Incomplete
Q11 = CMP-0077905-1: MOSFET, N-CH, 1000 V, 1.85 A, DPAK; Manufacturer: STMicroelectronics; Alternate Manufacturer: None; ChType: N; QgTyp_nC: 16; SizeAreaWB_mm2: 101.7114; SizeArea_mm2: 64.8114; IdsMax_A: 1.85A; VdsMax_V: 1kV; Vgs_V: 30V; AEC Category: Q101; Value: 1000V; SizeZ_mm: 2.29; SizeY_mm: 6.54; Value2: 16 nC; U/M: EA; Value1: ? ohm; SizeX_mm: 9.91
Q12 = ZXMN7A11GTA: MOSFET, N-CH, 70 V, 3.8 A, AEC-Q101, SOT-223; Manufacturer: Diodes Inc.; Alternate Manufacturer: None; U/M: EA; ChType: N; Value: 70V; VdsMax_V: 70; Value1: 0.19 ohm; Rdson45_ohm: 0.19; Value2: 7.4 nC; QgTyp_nC: 7.4; Vgs_V: 20; IdsMax_A: 3.8; SizeAreaWB_mm2: 76.5; SizeArea_mm2: 45.5; SizeX_mm: 6.5; SizeY_mm: 7; SizeZ_mm: 1.6; AEC Category: Q101; AEC Qualified: Y; Green_Lifecycle: Active; Green_REACh: Passed
R1 R2 = CRCW12061M00FKEA: RES, 1.00 M, 1%, 0.25 W, 1206; Manufacturer: Vishay-Dale; CompType: Resistor; Value: 1.00Meg; Res_ohm: 1000000; Value_Code: 1M00; Tolerance_%: 1; Power_W: 0.25; Value2: 0.25W; VDC_V: 200; TempCo: 100 ppm/C; SizeArea_mm2: 5.12; SizeX_mm: 3.2; SizeY_mm: 1.6; SizeZ_mm: 1.35; EIA_Code: E96; U/M: EA; AEC Category: Q200; Green_Lifecycle: Active; Green_REACh: Passed
R3-R24 = CRCW12061M00FKEA: RES, 1.00 M, 1%, 0.25 W, 1206; Manufacturer: Vishay-Dale; CompType: Resistor; Value: 1.00Meg; ValueDisplayed: 1.00M; Res_ohm: 1000000; Value_Code: 1M00; Tolerance_%: 1; Power_W: 0.25; Value2: 0.25W; VDC_V: 200; TempCo: 100 ppm/C; SizeArea_mm2: 5.12; SizeX_mm: 3.2; SizeY_mm: 1.6; SizeZ_mm: 1.35; EIA_Code: E96; U/M: EA; AEC Category: Q200; Green_Lifecycle: Active; Green_REACh: Passed
R25 = CRCW060310K0FKEA: RES, 10.0 k, 1%, 0.1 W, 0603; Manufacturer: Vishay-Dale; CompType: Resistor; Value: 10.0k; Res_ohm: 10000; Value_Code: 10k0; Tolerance_%: 1; Power_W: 0.1; Value2: 0.1W; VDC_V: 75; TempCo: 100 ppm/C; SizeArea_mm2: 1.28; SizeX_mm: 1.6; SizeY_mm: 0.8; EIA_Code: E96; U/M: EA; AEC Category: Q200; Green_Lifecycle: Active; Green_REACh: Passed
R35 = CRCW060380K6FKEA: RES, 80.6 k, 1%, 0.1 W, 0603; Manufacturer: Vishay-Dale; CompType: Resistor; Value: 80.6k; Res_ohm: 80600; Value_Code: 80k6; Tolerance_%: 1; Power_W: 0.1; Value2: 0.1W; VDC_V: 75; TempCo: 100 ppm/C; SizeArea_mm2: 1.28; SizeX_mm: 1.6; SizeY_mm: 0.8; EIA_Code: E96; U/M: EA; AEC Category: Q200; Green_Lifecycle: Active; Green_REACh: Passed
R36 = CRCW060328K0FKEA: RES, 28.0 k, 1%, 0.1 W, 0603; Manufacturer: Vishay-Dale; CompType: Resistor; Value: 28.0k; Res_ohm: 28000; Value_Code: 28k0; Tolerance_%: 1; Power_W: 0.1; Value2: 0.1W; VDC_V: 75; TempCo: 100 ppm/C; SizeArea_mm2: 1.28; SizeX_mm: 1.6; SizeY_mm: 0.8; EIA_Code: E96; U/M: EA; AEC Category: Q200; Green_Lifecycle: Active; Green_REACh: Passed
R37 = RC0603FR-0720RL: RES, 20.0, 1%, 0.1 W, 0603; Manufacturer: Yageo America; CompType: Resistor; Value: 20.0; Res_ohm: 20; Value_Code: 20R0; Tolerance_%: 1; Power_W: 0.1; Value2: 0.1W; VDC_V: 150; TempCo: 200 ppm/C; EIA_Code: E96; U/M: EA; AEC Category: Q200
R38 R39 = CRCW12062M00JNEA: RES, 2.0 M, 5%, 0.25 W, 1206; Manufacturer: Vishay-Dale; CompType: Resistor; Value: 2.0Meg; Res_ohm: 2000000; Value_Code: 2M00; Tolerance_%: 5; Power_W: 0.25; Value2: 0.25W; VDC_V: 200; TempCo: 200 ppm/C; SizeArea_mm2: 5.12; SizeX_mm: 3.2; SizeY_mm: 1.6; SizeZ_mm: 1.35; EIA_Code: E24; U/M: EA; AEC Category: Q200
R40 = RC1206FR-07300KL: RES, 300 k, 1%, 0.25 W, 1206; Manufacturer: Yageo America; CompType: Resistor; Value: 300k; Res_ohm: 300000; Tolerance_%: 1; Power_W: 0.25; Value2: 0.25W; VDC_V: 200; TempCo: 100 ppm/C; U/M: EA; AEC Category: Q200
R41 = ERJ-6GEYJ201V: RES, 200, 5%, 0.125 W, 0805; Manufacturer: Panasonic; CompType: Resistor; Value: 200; Value_Code: 200R; Tolerance_%: 5; Power_W: 0.125; Value2: 0.125W; VDC_V: 150; TempCo: 200 ppm/C; EIA_Code: E24; U/M: EA; AEC Category: Q200
R42 = CRCW06031K00FKEA: RES, 1.00k ohm, 1%, 0.1W, 0603; Manufacturer: Vishay-Dale; CompType: Resistor; Res_ohm: 1000; Value_Code: 1k00; Tolerance_%: 1; Power_W: 0.1; VDC_V: 75; TempCo: 100 ppm/C; EIA_Code: E96; U/M: EA
R43 = CRCW08052R70JNEA: RES, 2.7, 5%, 0.125 W, 0805; Manufacturer: Vishay-Dale; CompType: Resistor; Value: 2.7; Value_Code: 2R70; Tolerance_%: 5; Power_W: 0.125; Value2: 0.125W; VDC_V: 150; TempCo: 200 ppm/C; SizeArea_mm2: 2.5; SizeX_mm: 2; SizeY_mm: 1.25; SizeZ_mm: 1.45; EIA_Code: E24; U/M: EA; AEC Category: Q200
R44 = RC0603FR-0720K5L: RES, 20.5 k, 1%, 0.1 W, 0603; Manufacturer: Yageo America; CompType: Resistor; Value: 20.5k; Res_ohm: 20500; Value_Code: 20k5; Tolerance_%: 1; Power_W: 0.1; Value2: 0.1W; VDC_V: 150; TempCo: 200 ppm/C; SizeArea_mm2: 1.28; SizeX_mm: 1.6; SizeY_mm: 0.8; EIA_Code: E96; U/M: EA; AEC Category: Q200; Green_Lifecycle: Active; Green_REACh: Passed
R45 = RC0603FR-076K19L: RES, 6.19 k, 1%, 0.1 W, 0603; Manufacturer: Yageo America; CompType: Resistor; Value: 6.19k; Res_ohm: 6190; Value_Code: 6k19; Tolerance_%: 1; Power_W: 0.1; Value2: 0.1W; VDC_V: 150; TempCo: 200 ppm/C; SizeArea_mm2: 1.28; SizeX_mm: 1.6; SizeY_mm: 0.8; EIA_Code: E96; U/M: EA; AEC Category: Q200
R100-R102 R119 R121 R123 = RT0805BRD07361KL: RES, 361 k, 0.1%, 0.125 W, 0805; Manufacturer: Yageo America; CompType: Resistor; Value: 361k; Res_ohm: 361000; Tolerance_%: 0.1; Power_W: 0.125; Value2: 0.125W; VDC_V: 150; TempCo: 25 ppm/C; SizeArea_mm2: 2.5; SizeX_mm: 2; SizeY_mm: 1.25; SizeZ_mm: 1.45; EIA_Code: E192; U/M: EA; AEC Category: Q200
R105-R113 = CRCW1206330KJNEA: RES, 330 k, 5%, 0.25 W, 1206; Manufacturer: Vishay-Dale; CompType: Resistor; Value: 330k; Res_ohm: 330000; Tolerance_%: 5; Power_W: 0.25; Value2: 0.25W; VDC_V: 200; TempCo: 200 ppm/C; SizeArea_mm2: 5.12; SizeX_mm: 3.2; SizeY_mm: 1.6; SizeZ_mm: 1.35; EIA_Code: E24; U/M: EA; AEC Category: Q200
R116 = CRCW040210K0FKED: RES, 10.0k ohm, 1%, 0.063W, 0402; Manufacturer: Vishay-Dale; CompType: Resistor; Res_ohm: 10000; Value_Code: 10k0; Tolerance_%: 1; Power_W: 0.063; VDC_V: 50; TempCo: 100 ppm/C; EIA_Code: E96; U/M: EA
R117 = CRCW040212K7FKED: RES, 12.7k ohm, 1%, 0.063W, 0402; Manufacturer: Vishay-Dale; CompType: Resistor; Res_ohm: 12700; Value_Code: 12k7; Tolerance_%: 1; Power_W: 0.063; VDC_V: 50; TempCo: 100 ppm/C; EIA_Code: E96; U/M: EA
R118 R120 = CRCW12066R20JNEA: RES, 6.2, 5%, 0.25 W, 1206; Manufacturer: Vishay-Dale; CompType: Resistor; Value: 6.2; Value_Code: 6R20; Tolerance_%: 5; Power_W: 0.25; Value2: 0.25W; VDC_V: 200; TempCo: 200 ppm/C; SizeArea_mm2: 5.12; SizeX_mm: 3.2; SizeY_mm: 1.6; SizeZ_mm: 1.35; EIA_Code: E24; U/M: EA; AEC Category: Q200
R122 = RC0603FR-0710KL: RES, 10.0k ohm, 1%, 0.1W, 0603; Manufacturer: Yageo America; CompType: Resistor; Res_ohm: 10000; Value_Code: 10k0; Tolerance_%: 1; Power_W: 0.1; VDC_V: 150; TempCo: 200 ppm/C; EIA_Code: E96; U/M: EA
R124 = CRCW04025K49FKED: RES, 5.49k ohm, 1%, 0.063W, 0402; Manufacturer: Vishay-Dale; CompType: Resistor; Res_ohm: 5490; Value_Code: 5k49; Tolerance_%: 1; Power_W: 0.063; VDC_V: 50; TempCo: 100 ppm/C; EIA_Code: E96; U/M: EA
R125 = CRCW0402330KJNED: RES, 330k ohm, 5%, 0.063W, 0402; Manufacturer: Vishay-Dale; CompType: Resistor; Res_ohm: 330000; Tolerance_%: 5; Power_W: 0.063; VDC_V: 50; TempCo: 200 ppm/C; EIA_Code: E24; U/M: EA
RT100 RT101 = B59751B0120A070: Thermistor NTC, 50 ohm, 25%, D12.5xH16.5mm; Manufacturer: TDK; Value: 50; Tolerance_%: 25; TaMin_C: -40; TaMax_C: 125; U/M: EA
RV100 = S10K275E2: Varistor 275V RMS 10MM Radial, TH; Manufacturer: EPCOS Inc; SymbolCreator: a0412235
T1 = 7508110162: Transformer, TH; Manufacturer: Wurth Elektronik; SymbolCreator: a0411947
TP100 TP101 = 5000: Test Point, Miniature, Red, TH; Manufacturer: Keystone; CompType: Test Point Loop; U/M: EA
TP102 TP103 = 5001: Test Point, Miniature, Black, TH; Manufacturer: Keystone; CompType: Test Point Loop; U/M: EA
U1 = UCC28700QDBVRQ1: Constant-Voltage, Constant-Current Controller With Primary-Side Regulation, DBV0006A (SOT-23-6); Manufacturer: Texas Instruments; SymbolCreator: a0411947; SizeArea_mm2: 8.12; SizeAreaWB_mm2: 14.82; SizeX_mm: 2.8; SizeY_mm: 2.9; SizeZ_mm: 1.45; CompType: IC; U/M: EA
U2 = TL1963AQKTTRQ1: Single Output Fast Transient Response LDO, 1.5 A, Adjustable 1.21 to 20 V Output, 2.1 to 20 V Input, 5-pin DDPAK (KTT), -40 to 125 degC, Green (RoHS & no Sb/Br); Manufacturer: Texas Instruments; Alternate PartNumber: Equivalent; Iout(Max)(A): 1.5; Iq(Typ)(mA): 1; SubFamily: Single Channel LDO; Vdo(Typ)(mV): 340; Vin(Max)(V): 20; Vin(Min)(V): 2.1; Vout Adj(Min)(V): 1.21
U100 U102 U104 = ACS722LLCTR-10AB-T: High Accuracy, Galvanically Isolated Current Sensor IC, SOIC-8; Manufacturer: Allegro Microsystems Inc; SymbolCreator: Altium; SizeAreaWB_mm2: 55.131; SizeArea_mm2: 29.351; SizeX_mm: 5.99; SizeY_mm: 4.9; SizeZ_mm: 1.75
U101 = ACS716KLATR-12CB-NL-T: SENSOR CURRENT HALL 25A AC/DC; Manufacturer: Allegro Microsystems Inc; SymbolCreator: Altium
U103 = TLV71333PQDBVRQ1: Capacitor-Free, 150-mA, Low-Dropout Regulator with Foldback Current Limit for Portable Devices, DBV0005A; Manufacturer: Texas Instruments; SymbolCreator: Altium; SizeArea_mm2: 8.12; SizeAreaWB_mm2: 14.82; SizeX_mm: 2.8; SizeY_mm: 2.9; SizeZ_mm: 1.45; CompType: IC; U/M: EA

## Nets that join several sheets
PGND: PowerBoard_Control (46 pins), PowerBoard (86 pins)
3V3: PowerBoard_Control (R612.2), PowerBoard (17 pins)
5Vout: PowerBoard_Control (C614.1 U203.1 U203.3), PowerBoard (11 pins)
5Vp: PowerBoard_Control (8 pins), PowerBoard (7 pins)
AC_CUR_FAULT: PowerBoard_Control (J600.64), PowerBoard (C129.2 R125.2 U101.13)
AC_CUR_SENSE: PowerBoard_Control (R610.1), PowerBoard (U101.12)
AC_CUR_VREF: PowerBoard_Control (R604.2 R614.2), PowerBoard (C128.1 U101.10)
ACL_SENSE: PowerBoard_Control (C610.1 J600.20 R617.2), PowerBoard (R100.1)
ACN_SENSE: PowerBoard_Control (C609.1 J600.17 R616.2), PowerBoard (R123.1)
HVBUS: PowerBoard_Control (R602.2), PowerBoard (43 pins)
L100_CS: PowerBoard_Control (R600.1), PowerBoard (U100.7)
L101_CS: PowerBoard_Control (R603.1), PowerBoard (U102.7)
L102_CS: PowerBoard_Control (R608.1), PowerBoard (U104.7)
PFCG_1H: PowerBoard_Control (J600.53), PowerBoard (P1.3)
PFCG_1L: PowerBoard_Control (J600.55), PowerBoard (P1.6)
PFCG_2H: PowerBoard_Control (J600.50), PowerBoard (P2.3)
PFCG_2L: PowerBoard_Control (J600.52), PowerBoard (P2.6)
PFCG_3H: PowerBoard_Control (J600.54), PowerBoard (P3.3)
PFCG_3L: PowerBoard_Control (J600.56), PowerBoard (P3.6)
PFCG_4H: PowerBoard_Control (J600.49), PowerBoard (P4.3)
PFCG_4L: PowerBoard_Control (J600.51), PowerBoard (P4.6)
RELAY_CTRL: PowerBoard_Control (J600.57), PowerBoard (C120.1 Q12.1 R122.2)
RST_1: PowerBoard_Control (R621.1), PowerBoard (P1.4)
RST_2: PowerBoard_Control (R625.1), PowerBoard (P2.4)
RST_3: PowerBoard_Control (R626.1), PowerBoard (P3.4)
RST_4: PowerBoard_Control (R634.1), PowerBoard (P4.4)
SiC_F1: PowerBoard_Control (R618.2), PowerBoard (P1.1)
SiC_F2: PowerBoard_Control (R620.2), PowerBoard (P2.1)
SiC_F3: PowerBoard_Control (R624.2), PowerBoard (P3.1)
SiC_F4: PowerBoard_Control (R635.2), PowerBoard (P4.1)

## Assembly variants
001: not fitted FID1 FID2 FID3 R601 R612 R613 R615 R642 R643 U600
